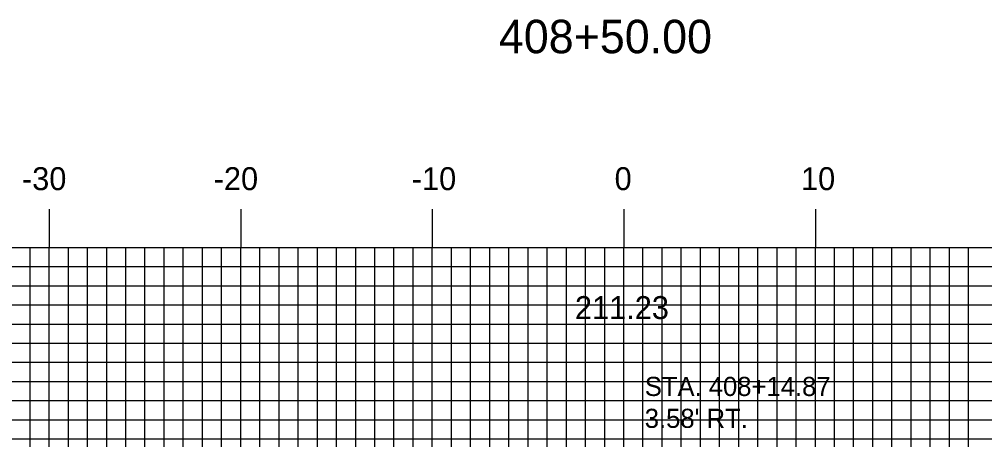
# Model space of a CAD drawing. Extents: x 852529 to 852872, y 364785 to 365005.
# Drawn here: x 852663.2 to 852713.6, y 364926.2 to 364948.2 of the extents above; entities that cross this region are included whole.
import ezdxf

# ---------------------------------------------------------------- set-up
doc = ezdxf.new("R2010")
doc.units = 0
for name, color, linetype in [('D_Roadway_Centerline_Text', 7, 'Continuous'), ('D_Text_Monospaced', 7, 'Continuous'), ('H_V ANNOTATION', 7, 'Continuous'), ('MAJOR', 7, 'Continuous'), ('MINOR', 7, 'Continuous')]:
    doc.layers.add(name, color=color, linetype=linetype)

msp = doc.modelspace()

# ---------------------------------------------------------------- linework, layer by layer
at = {"layer": 'MAJOR'}
for p, q in [((852664.731, 364938.237), (852664.731, 364936.233)), ((852674.731, 364938.237), (852674.731, 364936.233)), ((852684.731, 364938.237), (852684.731, 364936.233)), ((852694.731, 364938.237), (852694.731, 364936.233)), ((852704.731, 364938.237), (852704.731, 364936.233)), ((852554.731, 364936.233), (852834.731, 364936.233)), ((852554.731, 364936.233), (852834.731, 364936.233)), ((852664.731, 364906.233), (852664.731, 364936.233)), ((852674.731, 364906.233), (852674.731, 364936.233)), ((852684.731, 364906.233), (852684.731, 364936.233)), ((852694.731, 364906.233), (852694.731, 364936.233)), ((852704.731, 364906.233), (852704.731, 364936.233)), ((852554.731, 364931.233), (852834.731, 364931.233)), ((852554.731, 364926.233), (852834.731, 364926.233))]:
    msp.add_line(p, q, dxfattribs=at)
at = {"layer": 'MINOR'}
for p, q in [((852663.731, 364906.233), (852663.731, 364936.233)), ((852665.731, 364906.233), (852665.731, 364936.233)), ((852666.731, 364906.233), (852666.731, 364936.233)), ((852667.731, 364906.233), (852667.731, 364936.233)), ((852668.731, 364906.233), (852668.731, 364936.233)), ((852669.731, 364906.233), (852669.731, 364936.233)), ((852670.731, 364906.233), (852670.731, 364936.233)), ((852671.731, 364906.233), (852671.731, 364936.233)), ((852672.731, 364906.233), (852672.731, 364936.233)), ((852673.731, 364906.233), (852673.731, 364936.233)), ((852675.731, 364906.233), (852675.731, 364936.233)), ((852676.731, 364906.233), (852676.731, 364936.233)), ((852677.731, 364906.233), (852677.731, 364936.233)), ((852678.731, 364906.233), (852678.731, 364936.233)), ((852679.731, 364906.233), (852679.731, 364936.233)), ((852680.731, 364906.233), (852680.731, 364936.233)), ((852681.731, 364906.233), (852681.731, 364936.233)), ((852682.731, 364906.233), (852682.731, 364936.233)), ((852683.731, 364906.233), (852683.731, 364936.233)), ((852685.731, 364906.233), (852685.731, 364936.233)), ((852686.731, 364906.233), (852686.731, 364936.233)), ((852687.731, 364906.233), (852687.731, 364936.233)), ((852688.731, 364906.233), (852688.731, 364936.233)), ((852689.731, 364906.233), (852689.731, 364936.233)), ((852690.731, 364906.233), (852690.731, 364936.233)), ((852691.731, 364906.233), (852691.731, 364936.233)), ((852692.731, 364906.233), (852692.731, 364936.233)), ((852693.731, 364906.233), (852693.731, 364936.233)), ((852695.731, 364906.233), (852695.731, 364936.233)), ((852696.731, 364906.233), (852696.731, 364936.233)), ((852697.731, 364906.233), (852697.731, 364936.233)), ((852698.731, 364906.233), (852698.731, 364936.233)), ((852699.731, 364906.233), (852699.731, 364936.233)), ((852700.731, 364906.233), (852700.731, 364936.233)), ((852701.731, 364906.233), (852701.731, 364936.233)), ((852702.731, 364906.233), (852702.731, 364936.233)), ((852703.731, 364906.233), (852703.731, 364936.233)), ((852705.731, 364906.233), (852705.731, 364936.233)), ((852706.731, 364906.233), (852706.731, 364936.233)), ((852707.731, 364906.233), (852707.731, 364936.233)), ((852708.731, 364906.233), (852708.731, 364936.233)), ((852709.731, 364906.233), (852709.731, 364936.233)), ((852710.731, 364906.233), (852710.731, 364936.233)), ((852711.731, 364906.233), (852711.731, 364936.233)), ((852712.731, 364906.233), (852712.731, 364936.233)), ((852554.731, 364935.233), (852834.731, 364935.233)), ((852554.731, 364934.233), (852834.731, 364934.233)), ((852554.731, 364933.233), (852834.731, 364933.233)), ((852554.731, 364932.233), (852834.731, 364932.233)), ((852554.731, 364930.233), (852834.731, 364930.233)), ((852554.731, 364929.233), (852834.731, 364929.233)), ((852554.731, 364928.233), (852834.731, 364928.233)), ((852554.731, 364927.233), (852834.731, 364927.233))]:
    msp.add_line(p, q, dxfattribs=at)

# ---------------------------------------------------------------- texts
at = {"layer": 'D_Roadway_Centerline_Text'}
msp.add_text('211.23', height=1.2, dxfattribs=at).set_placement((852692.178, 364932.492))
at = {"layer": 'D_Text_Monospaced'}
for s, height, p in [('STA. 408+14.87', 0.99996, (852695.823, 364928.472)), ("3.58' RT.", 1, (852695.823, 364926.804))]:
    msp.add_text(s, height=height, dxfattribs=at).set_placement(p)
at = {"layer": 'H_V ANNOTATION'}
for s, height, p in [('408+50.00', 1.75, (852688.207, 364946.389)), ('-30', 1.2, (852663.307, 364939.233)), ('-20', 1.2, (852673.318, 364939.233)), ('-10', 1.2, (852683.66, 364939.233)), ('0', 1.2, (852694.249, 364939.233)), ('10', 1.2, (852703.981, 364939.233))]:
    msp.add_text(s, height=height, dxfattribs=at).set_placement(p)

doc.saveas('drawing.dxf')
